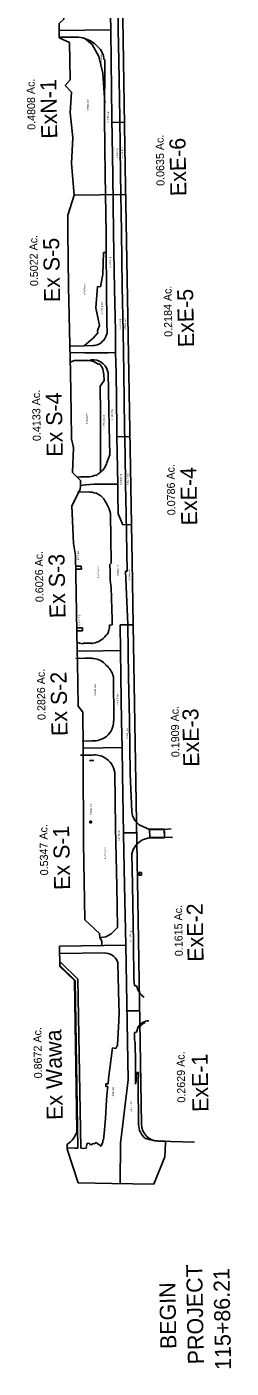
# Model space of a CAD drawing. Extents: x 925564 to 926134, y 853260 to 858402.
# Drawn here: x 925660 to 926018, y 853260 to 855606 of the extents above; entities that cross this region are included whole.
import ezdxf

# ---------------------------------------------------------------- set-up
doc = ezdxf.new("R2010")
doc.units = 0
for name, color, linetype in [('CGBack_ep', 7, 'Continuous'), ('CGep_ep', 7, 'Continuous'), ('ConcSlabs_ep', 7, 'Continuous'), ('DrainDivides01', 7, 'Continuous'), ('NonPlottingEle_dp', 7, 'Continuous'), ('PavtAsphalt_ep', 7, 'Continuous'), ('PavtMisc_ep', 7, 'Continuous'), ('SidewalkBack_ep', 7, 'Continuous'), ('TextLabel', 7, 'Continuous')]:
    doc.layers.add(name, color=color, linetype=linetype)

msp = doc.modelspace()

# ---------------------------------------------------------------- linework, layer by layer
at = {"layer": 'CGBack_ep'}
for p, q in [((925788.4, 853649.1), (925784.5, 853652.2)), ((925793.1, 853655.8), (925791, 853649.4)), ((925793.4, 853658.7), (925793.1, 853655.8)), ((925744.3, 853644.6), (925749.6, 853644.5)), ((925754.6, 853644.5), (925759.3, 853644.4))]:
    msp.add_line(p, q, dxfattribs=at)
msp.add_ellipse((925789.6, 853650), major_axis=(-0.6, -1.37), ratio=0.998698, start_param=5.766555, end_param=7.891986, dxfattribs=at)
at = {"layer": 'CGep_ep'}
msp.add_line((925850.4, 853756.4), (925851.4, 853762.7), dxfattribs=at)
at = {"layer": 'ConcSlabs_ep'}
for p, q in [((925798.8, 853757.4), (925798.5, 853752.7)), ((925798.5, 853752.7), (925802.2, 853752.4)), ((925802.4, 853757.1), (925798.8, 853757.4))]:
    msp.add_line(p, q, dxfattribs=at)
at = {"layer": 'DrainDivides01'}
for p, q in [((925821.4, 856018.6), (925832.6, 855359.6)), ((925806.2, 855653.9), (925807.1, 855600.1)), ((925716.8, 855599.3), (925807.1, 855600.7)), ((925807.1, 855600.1), (925807.9, 855546.6)), ((925807.9, 855546.6), (925809.2, 855446.3)), ((925809.2, 855446.3), (925810.9, 855346.4)), ((925809.3, 855438.7), (925831.2, 855439.1)), ((925832.6, 855359.6), (925833.1, 855329.6)), ((925810.9, 855346.4), (925812.2, 855245.8)), ((925731.9, 855276.7), (925743.4, 855311.4)), ((925833.4, 855312.9), (925743.4, 855311.4)), ((925833.1, 855329.6), (925843.2, 854735.4)), ((925731.9, 855276.7), (925732.1, 855247.7)), ((925733.2, 855151.4), (925732.1, 855247.7)), ((925812.2, 855245.8), (925813.6, 855147.1)), ((925735.2, 855075.1), (925733.2, 855151.4)), ((925813.6, 855147.1), (925815.2, 855074.5)), ((925736.5, 855001.1), (925735.2, 855075.1)), ((925815.2, 855074.5), (925815.3, 855036.5)), ((925815.3, 855036.5), (925816.6, 855001.5)), ((925737.8, 854931.8), (925736.5, 855001.1)), ((925816.6, 855001.5), (925817.5, 854904.3)), ((925738.5, 854884.8), (925737.8, 854931.8)), ((925817.5, 854904.3), (925817.8, 854888.8)), ((925817.8, 854888.8), (925840.6, 854889.2)), ((925843.2, 854735.4), (925844.3, 854671.2)), ((925844.3, 854671.2), (925846.2, 854560.3)), ((925823.4, 854559.9), (925846.2, 854560.3)), ((925823.4, 854559.9), (925823.9, 854515.4)), ((925855.6, 854009.3), (925846.2, 854560.3)), ((925823.9, 854515.4), (925824.9, 854469.5)), ((925824.9, 854469.5), (925826.1, 854391.7)), ((925826.1, 854391.7), (925827.1, 854345.6)), ((925758.6, 854344.5), (925827.1, 854345.6)), ((925827.1, 854345.6), (925827.8, 854298.4)), ((925827.8, 854298.4), (925829.7, 854194.7)), ((925852.4, 854196.4), (925829.7, 854196.1)), ((925829.7, 854194.7), (925831, 854104.9)), ((925759.6, 854178.2), (925761.9, 854044.1)), ((925831, 854104.9), (925833.3, 853999.5)), ((925717.7, 853998.1), (925833.3, 853999.5)), ((925833.3, 854002.1), (925833.3, 853999.5)), ((925833.3, 853999.5), (925837.3, 853764)), ((925861, 853686.5), (925855.6, 854009.3)), ((925748, 853675.1), (925743.7, 853937.8)), ((925857.7, 853885.1), (925835.3, 853884.8)), ((925824.4, 853653.6), (925837.3, 853764)), ((925730.9, 853651.5), (925731, 853646)), ((925731, 853646), (925731, 853643.1)), ((925824.4, 853653.6), (925823.3, 853582.7)), ((925902.7, 853656.7), (925890.1, 853657)), ((925731, 853643.1), (925750.1, 853583.9))]:
    msp.add_line(p, q, dxfattribs=at)
for points in [[(925734.8, 855578.3), (925717, 855586.9), (925716.6, 855611.7), (925725.2, 855619.6), (925724.9, 855632.4), (925726.8, 855640.3)], [(925743.4, 855311.4), (925738.4, 855367.1), (925740.9, 855411.7), (925736.3, 855456.1), (925738.5, 855491.9), (925727.5, 855503.5), (925735.9, 855513.2), (925735.3, 855547.6), (925734.8, 855578.3)], [(925735.9, 855036.3), (925761.6, 855036)], [(925761.6, 855036), (925802.8, 855035.7)], [(925802.8, 855035.7), (925815.3, 855036.5)], [(925738.5, 854884.8), (925740.8, 854875.4), (925742, 854869.8), (925740.4, 854826.3), (925754.4, 854812.7), (925754.1, 854803.9)], [(925817.8, 854888.8), (925819.3, 854806.3)], [(925754.1, 854803.9), (925753.9, 854796.9), (925739, 854768.2)], [(925819.3, 854806.3), (925777.5, 854805.8), (925763.5, 854804.7), (925758.6, 854804.3), (925754.1, 854803.9)], [(925819.3, 854806.3), (925819.6, 854787.4), (925820.2, 854754)], [(925748.5, 854514.7), (925745.6, 854681.2), (925741.7, 854702.5), (925739, 854768.2)], [(925820.2, 854754), (925828.3, 854735.1), (925843.2, 854735.4)], [(925748.5, 854514.7), (925762.1, 854514.2), (925823.9, 854515.4)], [(925758.6, 854344.5), (925758.3, 854407.1), (925750.1, 854417.6), (925748.8, 854495), (925748.5, 854514.7)], [(925759.6, 854178.2), (925758.7, 854330.4), (925758.6, 854344.5)], [(925791.8, 853999), (925791.3, 854006), (925787.8, 854013.5), (925787.7, 854020.3), (925761.9, 854044.1)], [(925743.7, 853937.8), (925718.3, 853962.4), (925717.7, 853998.1)], [(925750.1, 853583.9), (925809, 853583), (925882.4, 853581.8), (925902, 853629.3), (925902.7, 853653.9), (925902.7, 853656.7)]]:
    msp.add_lwpolyline(points, dxfattribs=at)
for centre, radius, start, end in [((925712.8, 853682.7), 36, 300.0194, 347.8836), ((925891, 853687), 30, 180.9738, 268.3014)]:
    msp.add_arc(centre, radius, start, end, dxfattribs=at)
at = {"layer": 'NonPlottingEle_dp'}
for p, q in [((925843.2, 854735.4), (925844.3, 854671.2)), ((925844.3, 854671.2), (925846.2, 854560.3)), ((925846.2, 854560.3), (925823.4, 854559.9)), ((925823.4, 854559.9), (925823.9, 854515.4))]:
    msp.add_line(p, q, dxfattribs=at)
for points in [[(925739, 854768.2), (925753.9, 854796.9), (925754.1, 854803.9)], [(925754.1, 854803.9), (925758.6, 854804.3), (925763.5, 854804.7), (925777.5, 854805.8), (925819.3, 854806.3)], [(925819.3, 854806.3), (925819.6, 854787.4), (925820.2, 854754)], [(925748.5, 854514.7), (925745.6, 854681.2), (925741.7, 854702.5), (925739, 854768.2)], [(925820.2, 854754), (925828.3, 854735.1), (925843.2, 854735.4)], [(925823.9, 854515.4), (925762.1, 854514.2), (925748.5, 854514.7)]]:
    msp.add_lwpolyline(points, dxfattribs=at)
at = {"layer": 'PavtAsphalt_ep'}
for p, q in [((925795.4, 853986.1), (925799, 853985.9)), ((925821.3, 853897.1), (925819.8, 853968.3)), ((925847.7, 853940.7), (925848.5, 853928.9)), ((925848.5, 853928.9), (925852.4, 853928.7)), ((925821.3, 853897.1), (925821.7, 853882)), ((925821.7, 853882), (925821.5, 853867.2)), ((925821.5, 853867.2), (925818.9, 853825.1)), ((925852.1, 853847.3), (925854.9, 853856.8)), ((925848.8, 853834), (925848.9, 853847)), ((925849.6, 853829.5), (925848.8, 853834)), ((925848.9, 853847), (925852.1, 853847.3)), ((925809.9, 853819.9), (925803.2, 853765.9)), ((925816.2, 853819.3), (925809.9, 853819.9)), ((925818.9, 853825.1), (925816.2, 853819.3)), ((925850.4, 853794.1), (925849.6, 853829.5)), ((925850.4, 853756.4), (925850.4, 853794.1)), ((925802.4, 853757.1), (925803.2, 853765.9)), ((925799.6, 853729.4), (925800.9, 853743.3)), ((925800.9, 853743.3), (925802.2, 853752.4)), ((925799.6, 853729.4), (925798.2, 853696.3)), ((925795.6, 853670.3), (925798.2, 853696.3)), ((925795.6, 853670.3), (925794.3, 853659.1)), ((925793.4, 853658.7), (925794.3, 853659.1))]:
    msp.add_line(p, q, dxfattribs=at)
for centre, major_axis, ratio, start_param, end_param in [((925882.7, 853934.6), (-6.4, 30.3), 0.997873, 1.554304, 2.336277), ((925873.8, 853845.3), (-21.2, 6.3), 0.999329, 4.996946, 6.023145)]:
    msp.add_ellipse(centre, major_axis=major_axis, ratio=ratio, start_param=start_param, end_param=end_param, dxfattribs=at)
at = {"layer": 'PavtMisc_ep'}
for p, q in [((925819.3, 855653.9), (925820, 855601.1)), ((925820, 855601.1), (925821.4, 855546.5)), ((925717, 855587.7), (925747.9, 855587.7)), ((925761.7, 855585.3), (925761.6, 855585.4)), ((925784.6, 855570.9), (925783.3, 855572.1)), ((925795.8, 855548.2), (925796.7, 855548.2)), ((925796.7, 855548.2), (925796.4, 855446.7)), ((925821.4, 855546.5), (925822.8, 855446.4)), ((925796.4, 855446.7), (925797.1, 855346.4)), ((925822.8, 855446.4), (925824.4, 855346.8)), ((925797.1, 855346.4), (925799, 855245.5)), ((925824.4, 855346.8), (925825.9, 855246.6)), ((925799, 855245.5), (925798.9, 855211.2)), ((925825.9, 855246.6), (925827.2, 855151.8)), ((925793, 855172.5), (925794.5, 855211.2)), ((925794.5, 855211.2), (925798.9, 855211.2)), ((925798.9, 855211.2), (925799.8, 855151.8)), ((925789, 855151), (925793, 855172.5)), ((925781.2, 855114.2), (925784.1, 855151.5)), ((925784.1, 855151.5), (925789, 855151)), ((925800.4, 855084.9), (925799.8, 855151.8)), ((925827.2, 855151.8), (925828.6, 855072.4)), ((925781.2, 855114.2), (925787.2, 855083.7)), ((925787.2, 855083.7), (925784.2, 855074.9)), ((925801, 855074.6), (925800.4, 855084.9)), ((925760.5, 855048.1), (925777, 855062)), ((925777, 855062), (925784.7, 855070.6)), ((925784.7, 855070.6), (925784.2, 855074.9)), ((925828.6, 855072.4), (925829.2, 855036.8)), ((925735.7, 855047.6), (925760.5, 855048.1)), ((925760.5, 855048.1), (925775.5, 855048.3)), ((925775.5, 855048.3), (925775.7, 855048.4)), ((925829.2, 855036.8), (925829.8, 855000.7)), ((925743.6, 855022.1), (925736.2, 855019.5)), ((925767.4, 855022.6), (925743.6, 855022.1)), ((925785.5, 855015.4), (925787.1, 855016.8)), ((925793.1, 855007.2), (925795.3, 854997.9)), ((925802.5, 855000.7), (925799.4, 855009.3)), ((925795.4, 854987.4), (925788.5, 854977.6)), ((925795.3, 854997.9), (925795.4, 854987.4)), ((925804.5, 854906.2), (925802.5, 855000.7)), ((925829.8, 855000.7), (925831.4, 854904.5)), ((925788.5, 854977.6), (925789.4, 854930.4)), ((925789.4, 854930.4), (925788.9, 854826.7)), ((925805.4, 854857.3), (925804.5, 854906.2)), ((925831.4, 854904.5), (925832.1, 854858.5)), ((925799.4, 854841.9), (925805.4, 854857.3)), ((925832.1, 854858.5), (925833.1, 854806.8)), ((925754.2, 854818.7), (925748.4, 854818.5)), ((925769.8, 854819.1), (925754.2, 854818.7)), ((925781.2, 854822), (925781.4, 854821.4)), ((925833.1, 854806.8), (925832.9, 854805.8)), ((925832.9, 854805.8), (925834, 854753.7)), ((925748.8, 854792.3), (925767.8, 854792.6)), ((925780.8, 854790.3), (925781.1, 854790.7)), ((925807.8, 854668.1), (925806.6, 854755)), ((925835.7, 854653.9), (925834, 854753.7)), ((925835.7, 854653.9), (925834, 854753.7)), ((925746, 854662.4), (925755.5, 854662.6)), ((925746, 854662.4), (925746, 854657.5)), ((925755.7, 854657.6), (925746, 854657.5)), ((925755.5, 854662.6), (925755.7, 854657.6)), ((925805.4, 854665.6), (925807.8, 854668.1)), ((925805.9, 854652.7), (925805.4, 854665.6)), ((925806.3, 854637.9), (925805.9, 854652.7)), ((925808.1, 854625.2), (925806.3, 854637.9)), ((925832.8, 854653.7), (925835.7, 854653.9)), ((925836.8, 854560.5), (925832.8, 854653.7)), ((925836.8, 854560.5), (925832.8, 854653.7)), ((925809.6, 854569.5), (925808.1, 854625.2)), ((925809.8, 854560.3), (925809.6, 854569.5)), ((925837.4, 854514.5), (925836.8, 854560.5)), ((925837.4, 854514.5), (925836.8, 854560.5)), ((925747.5, 854554.6), (925757.6, 854554.9)), ((925747.5, 854554.6), (925747.7, 854549.4)), ((925757.7, 854549.6), (925747.7, 854549.4)), ((925757.6, 854554.9), (925757.7, 854549.6)), ((925798.5, 854541.2), (925800.1, 854543.2)), ((925800.1, 854543.2), (925800.5, 854542.7)), ((925809.8, 854560.3), (925805, 854559.7)), ((925758.7, 854527.8), (925763.3, 854527.8)), ((925758.7, 854527.8), (925758.7, 854527.1)), ((925763.3, 854527.8), (925773.1, 854527.9)), ((925773.1, 854527.9), (925773.8, 854528)), ((925773.8, 854528), (925773.9, 854527.4)), ((925773.9, 854527.4), (925776, 854527.4)), ((925775.8, 854528.1), (925776.6, 854528.1)), ((925776, 854527.4), (925775.8, 854528.1)), ((925838.3, 854468.8), (925837.4, 854514.5)), ((925838.3, 854468.8), (925837.4, 854514.5)), ((925745.8, 854501.1), (925761.7, 854501.5)), ((925761.7, 854501.5), (925774, 854501.5)), ((925774, 854501.8), (925774.9, 854501.9)), ((925774, 854501.5), (925774, 854501.8)), ((925774.8, 854501.4), (925774.9, 854501.9)), ((925774.8, 854501.4), (925777, 854501.3)), ((925798.9, 854489.4), (925800.2, 854488)), ((925800.2, 854488), (925800.8, 854488.3)), ((925812.3, 854392), (925811.7, 854469.3)), ((925839.9, 854393.2), (925838.3, 854468.8)), ((925839.9, 854393.2), (925838.3, 854468.8)), ((925840.5, 854347.4), (925839.9, 854393.2)), ((925840.5, 854347.4), (925839.9, 854393.2)), ((925757.2, 854356.8), (925774.3, 854357.1)), ((925754, 854332.1), (925774.8, 854332.3)), ((925841.3, 854300), (925840.5, 854347.4)), ((925841.3, 854300), (925840.5, 854347.4)), ((925769.9, 854322.8), (925777.6, 854322.9)), ((925815.4, 854204.8), (925814, 854302)), ((925843.8, 854232.8), (925841.3, 854300)), ((925843.8, 854232.8), (925841.3, 854300)), ((925770.4, 854213.5), (925770.6, 854216.4)), ((925773.4, 854213.5), (925770.4, 854213.5)), ((925770.6, 854216.4), (925773.4, 854216.4)), ((925773.4, 854216.4), (925773.4, 854213.5)), ((925857, 854210.1), (925874.7, 854202.1)), ((925817.6, 854103.2), (925815.4, 854204.8)), ((925862.7, 854184.1), (925875.2, 854188.1)), ((925875.2, 854188.1), (925874.7, 854202.1)), ((925900.7, 854203.4), (925875, 854202.9)), ((925875, 854202.9), (925875, 854202.8)), ((925875, 854202.8), (925875.1, 854201.9)), ((925900.8, 854202.2), (925875, 854201.8)), ((925875, 854201.8), (925875.4, 854187.9)), ((925875.1, 854201.9), (925900.7, 854202.4)), ((925875.3, 854187.8), (925901.1, 854188.2)), ((925875.3, 854187.8), (925875.4, 854187.9)), ((925875.4, 854186.9), (925875.3, 854187.8)), ((925875.4, 854187.9), (925901, 854188.4)), ((925901.1, 854187.4), (925875.4, 854186.9)), ((925875.4, 854186.7), (925901.2, 854187.3)), ((925875.4, 854186.9), (925875.4, 854186.7)), ((925900.7, 854203.2), (925900.7, 854203.4)), ((925900.7, 854202.4), (925900.7, 854203.2)), ((925900.8, 854202.2), (925913, 854203.2)), ((925900.9, 854195.4), (925900.8, 854202.2)), ((925901, 854188.4), (925900.8, 854202.2)), ((925901, 854188.4), (925900.9, 854195.4)), ((925901.1, 854188.2), (925901, 854188.4)), ((925901, 854188.4), (925915.3, 854188.2)), ((925901.1, 854188.2), (925901.1, 854187.4)), ((925901.2, 854187.3), (925901.1, 854187.4)), ((925845, 854105.2), (925844, 854159.3)), ((925845, 854105.2), (925844, 854159.3)), ((925857, 854122.1), (925857, 854126.6)), ((925857, 854126.6), (925861, 854126.6)), ((925860.9, 854121.9), (925857, 854122.1)), ((925861, 854126.6), (925860.9, 854121.9)), ((925818.7, 854030.5), (925817.6, 854103.2)), ((925846.9, 854002.6), (925845, 854105.2)), ((925846.9, 854002.6), (925845, 854105.2)), ((925818.7, 854030.5), (925808.1, 854019.8)), ((925789.8, 854013.2), (925786.7, 854013.2)), ((925798.7, 854014.6), (925789.8, 854013.2)), ((925808.1, 854019.8), (925798.7, 854014.6)), ((925847.7, 853940.7), (925846.9, 854002.6)), ((925847.7, 853940.7), (925846.9, 854002.6)), ((925717.9, 853985), (925795.4, 853986.1)), ((925852.8, 853777), (925851.4, 853762.7)), ((925855.9, 853776.8), (925852.8, 853777)), ((925855.2, 853759.1), (925855.9, 853776.8)), ((925855.8, 853685.9), (925855.2, 853759.1)), ((925953.8, 853655.1), (925892, 853657))]:
    msp.add_line(p, q, dxfattribs=at)
msp.add_lwpolyline([(925796.5, 855472.9), (925793.3, 855524.8), (925786, 855553.9), (925774.5, 855575.2), (925761.7, 855585.3)], dxfattribs=at)
for centre, major_axis, ratio, start_param, end_param in [((925749.8, 855557.6), (29.7, 4.9), 0.999389, 1.00653, 1.471707), ((925748.4, 855539.4), (44.8, 16.9), 0.999456, 0.392947, 0.929094), ((925761.8, 855545.5), (-31.6, -12.6), 0.999822, 2.840052, 3.600689), ((925772.2, 855076), (-7.4, 27.9), 0.999919, 3.399347, 4.406577), ((925775.8, 855072.1), (-14.3, -19), 0.997949, 0.637462, 1.107776), ((925766.8, 854994.5), (24.6, -14.2), 0.98579, 1.365372, 2.067748), ((925776.4, 854997.7), (12.1, -22.8), 0.998662, 1.544457, 2.93738), ((925765.2, 854996.3), (2.3, 29.9), 0.999352, 5.161217, 5.541352), ((925769.5, 854838.4), (-35.3, -8), 0.52537, 1.459004, 1.785438), ((925743.8, 854881.2), (63.7, 39.8), 0.940948, 4.715793, 4.838569), ((925774, 854848.3), (-5.3, -25.8), 0.996113, 0.810458, 1.526232), ((925766.7, 854755.5), (-46.9, 5.5), 0.784213, 4.500196, 4.781231), ((925768.7, 854759.6), (-31.9, 11), 0.991636, 4.266447, 4.663622), ((925732.1, 854735.1), (20.7, -74.9), 0.993047, 1.562404, 1.975382), ((925771.5, 854561.4), (33.6, 2.9), 0.998291, 4.779391, 5.554684), ((925769.1, 854560.1), (9, 34.9), 0.997303, 4.4608, 4.954516), ((925758.2, 854545.1), (18, -1.4), 0.999732, 4.121502, 4.824069), ((925773.4, 854468.5), (-17.9, 27.8), 0.996019, 4.826241, 5.59831), ((925771.8, 854459), (12.6, -39.3), 0.997559, 1.51233, 2.050093), ((925777.2, 854391.8), (-5.4, 34.6), 0.999796, 3.678582, 4.56208), ((925776.1, 854396.1), (-38.9, -4.2), 0.998997, 1.41617, 2.105942), ((925778.5, 854297), (-35.3, -3.8), 0.999762, 4.06904, 4.709356), ((925779.4, 854297.1), (-25.2, -24.2), 0.999952, 2.514878, 3.430744), ((925878.3, 854237.6), (28.9, -19.5), 0.999004, 3.875568, 4.647025), ((925878.3, 854237.6), (28.9, -19.5), 0.999004, 3.875568, 4.647025), ((925880.4, 854151.2), (32.4, -18.5), 0.999665, 2.584277, 3.441629), ((925880.4, 854151.2), (32.4, -18.5), 0.999665, 2.584277, 3.441629), ((925796.5, 853961.8), (-0.3, 24.3), 0.999055, 4.971951, 6.162689), ((925868.5, 853853), (-1.3, -10.6), 0.997713, 3.36443, 5.031975), ((925885.8, 853685.8), (-29.3, 6.4), 0.999709, 0.209542, 1.143327), ((925896.8, 853744.5), (87.8, 3.9), 0.996393, 4.332222, 4.613167)]:
    msp.add_ellipse(centre, major_axis=major_axis, ratio=ratio, start_param=start_param, end_param=end_param, dxfattribs=at)
at = {"layer": 'SidewalkBack_ep'}
for p, q in [((925720.7, 853968.4), (925718.2, 853968.4)), ((925718.7, 853963.4), (925718.3, 853963.4)), ((925749.6, 853644.5), (925744.7, 853938.2)), ((925754.6, 853644.5), (925749.7, 853940.4)), ((925763.3, 853647.4), (925765.5, 853649.5)), ((925765, 853645.6), (925763.3, 853647.4)), ((925763.9, 853644.8), (925765, 853645.6)), ((925765.5, 853649.5), (925765.9, 853653.3)), ((925765.9, 853653.3), (925770.4, 853652.8)), ((925770.4, 853652.8), (925770.3, 853650.9)), ((925770.3, 853650.9), (925773.8, 853650.4)), ((925773.8, 853650.4), (925775.2, 853652.9)), ((925775.2, 853652.9), (925777.9, 853652)), ((925777.9, 853652), (925781.4, 853654.6)), ((925781.4, 853654.6), (925784.5, 853652.2)), ((925731, 853645), (925744.3, 853644.6)), ((925759.3, 853644.4), (925763.9, 853644.8))]:
    msp.add_line(p, q, dxfattribs=at)
for points in [[(925744.7, 853938.2), (925718.7, 853963.4)], [(925749.7, 853940.4), (925720.7, 853968.4)]]:
    msp.add_lwpolyline(points, dxfattribs=at)

# ---------------------------------------------------------------- texts
at = {"layer": 'TextLabel'}
for s, height, p in [('0.0120 gravel', 2.8, (925792.1, 855534.4)), ('0.4808 Ac.', 14, (925675.5, 855425.9)), ('ExN-1', 28, (925713.6, 855410.6)), ('0.3526 perv', 2.8, (925768.6, 855458.9)), ('0.1162 imp', 2.8, (925803.6, 855438.8)), ('0.0635 Ac.', 14, (925901.2, 855327.9)), ('ExE-6', 28, (925939.5, 855310)), ('0.0391 imp', 2.8, (925819.7, 855376.5)), ('0.0244 perv', 2.8, (925828.8, 855375.7)), ('0.5022 Ac.', 14, (925680.2, 855152.5)), ('Ex S-5', 28, (925718.7, 855124.7)), ('0.1094 imp', 2.8, (925807.9, 855184.5)), ('0.3426 perv', 2.8, (925762.9, 855137.3)), ('0.2184 Ac.', 14, (925914.9, 855063.9)), ('0.0502 gravel', 2.8, (925793.3, 855102.8)), ('ExE-5', 28, (925953, 855045.8)), ('0.1324 imp', 2.8, (925824.9, 855075.9)), ('0.0826 perv', 2.8, (925833.8, 855076.4)), ('0.4133 Ac.', 14, (925684.8, 854881.6)), ('Ex S-4', 28, (925723.3, 854854.3)), ('0.2364 perv', 2.8, (925766.7, 854910.9)), ('0.0576 gravel', 2.8, (925796.7, 854903.7)), ('0.1193 imp', 2.8, (925811.3, 854917.4)), ('0.0469 imp', 2.8, (925826.4, 854805)), ('0.0317 perv', 2.8, (925838.5, 854804.6)), ('0.0786 Ac.', 14, (925920.2, 854751.8)), ('ExE-4', 28, (925958.5, 854734.2)), ('0.6026 Ac.', 14, (925689.6, 854599.8)), ('Ex S-3', 28, (925728.1, 854571.9)), ('0.0012 imp', 2.8, (925751.8, 854670)), ('0.3623 perv', 2.8, (925786.4, 854641.8)), ('0.1985 imp', 2.8, (925821, 854645.9)), ('0.0394 perv', 2.8, (925841.2, 854637)), ('0.0012 imp', 2.8, (925753.7, 854559)), ('0.2826 Ac.', 14, (925693.1, 854393.7)), ('Ex S-2', 28, (925731.6, 854365.8)), ('0.1821 perv', 2.8, (925781.4, 854436.2)), ('0.1005 imp', 2.8, (925820.7, 854420.5)), ('0.1909 Ac.', 14, (925927.4, 854328.7)), ('ExE-3', 28, (925962.1, 854312)), ('0.1197 imp', 2.8, (925837.3, 854361.5)), ('0.0001 imp', 2.8, (925773.8, 854228.4)), ('0.5347 Ac.', 14, (925697.7, 854122)), ('Ex S-1', 28, (925736.2, 854096.6)), ('0.1446 imp', 2.8, (925823.1, 854182.6)), ('0.3900 perv', 2.8, (925798.6, 854150.3)), ('0.1615 Ac.', 14, (925933.3, 853980.6)), ('ExE-2', 28, (925969.6, 853971.1)), ('0.1118 imp', 2.8, (925843.4, 854005.7)), ('0.8672 Ac.', 14, (925687.1, 853767)), ('Ex Wawa', 28, (925723.3, 853694.3)), ('0.2629 Ac.', 14, (925937.7, 853724.5)), ('ExE-1', 28, (925978.2, 853708.4)), ('0.3806 imp', 2.8, (925813, 853732.5)), ('0.2327 imp', 2.8, (925844.1, 853708.1)), ('PROJECT ', 28, (925970.1, 853267)), ('115+86.21', 28, (926017.8, 853257.1)), ('BEGIN ', 28, (925922, 853293.7))]:
    msp.add_text(s, height=height, rotation=91.0261, dxfattribs=at).set_placement(p)

doc.saveas('drawing.dxf')
